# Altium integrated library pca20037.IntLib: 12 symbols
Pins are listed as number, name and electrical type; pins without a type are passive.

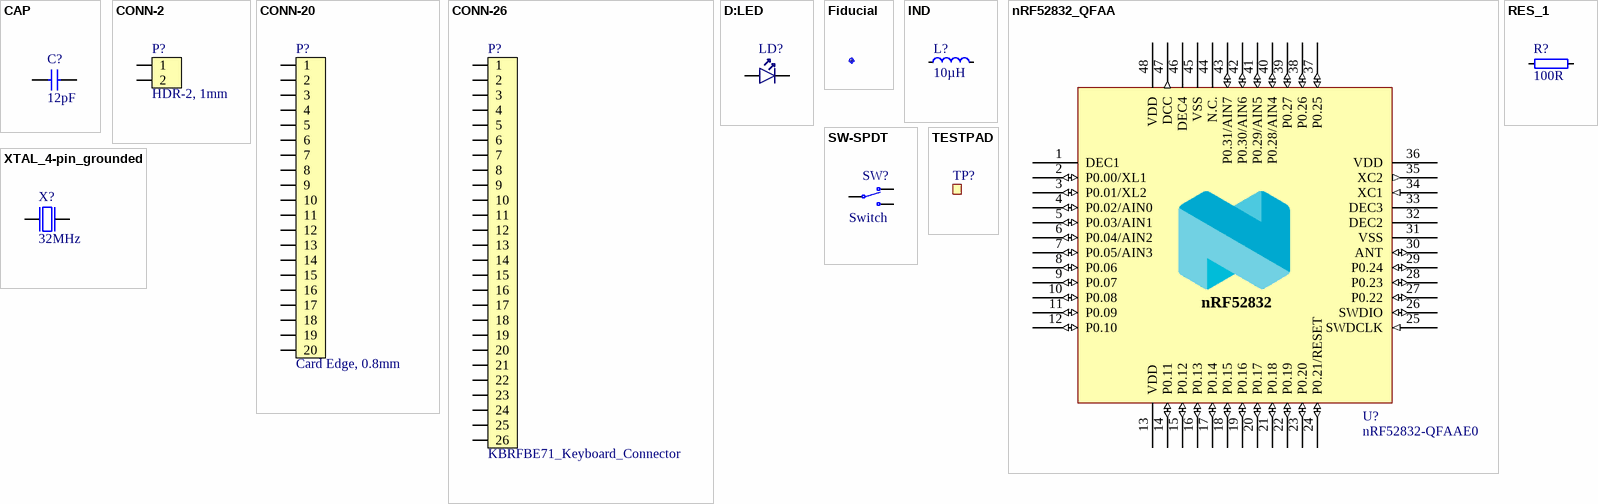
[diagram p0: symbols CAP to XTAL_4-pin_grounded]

## CAP
designator C?, comment 12pF
Capacitor, NP0, ±2%; Part Number: C0402-12p; Part number IPS: 00000002398; Note: 50V; Artikkelnr Noca: 20029159
footprint CAPC1005X04L
pins: 1, 2

## CONN-2
designator P?, comment HDR-2, 1mm
1.0mm pitch connector side entry SMD; Part Number: SM02B-SRSS-TB; Manufacturer: JST; Manufacturer Part Number: SM02B-SRSS-TB(LF)(SN); Part number IPS: 00000007791; Note: JST, Header; Artikkelnr Noca: 55010030
footprint SM02B-SRSS-TB
pins: 1, 2

## CONN-20
designator P?, comment Card Edge, 0.8mm
0.8mm pitch, dual edge, right angle, SMD, card edge connector; Part Number: 10056847-101LF; Manufacturer: FCI; Artikkelnr Noca: N.A.
footprint 10056847-101LF
pins: 1, 2, 3, 4, 5, 6, 7, 8, 9, 10, 11, 12, 13, 14, 15, 16, 17, 18, 19, 20

## CONN-26
designator P?, comment KBRFBE71_Keyboard_Connector
KBRFBE71 Keyboard Connector; Artikkelnr Noca: N.A.
footprint KBRFBE71_Keyboard_Connector
pins: 1, 2, 3, 4, 5, 6, 7, 8, 9, 10, 11, 12, 13, 14, 15, 16, 17, 18, 19, 20, 21, 22, 23, 24, 25, 26

## D:LED
designator LD?, comment L0603R  (value not drawn)
LED 0603, EL19-21SURC; Manufacturer: Everlight; Manufacturer Part Number: EL-19-21SURC/S530-A2/TR8; Part number IPS: N.A.; Note: 39 mcd @ 20 mA; Artikkelnr Noca: 13019043
footprint LED_0603_R
pins: 1 C, 2 A

## Fiducial
designator Fiducual?, comment Fiducial mark  (value not drawn)
Part Number: Fid-Mark; Artikkelnr Noca: N.A.
footprint Fiducial

## IND
designator L?, comment 10µH
Inductor, 80mA, ±10%; Part Number: L0603-10µ; Manufacturer: Taiyo Yuden; Manufacturer Part Number: LBMF1608T100K; Part number IPS: 00000007794; Note: LBMF1608T100K 10µH 80mA 0603; Artikkelnr Noca: 33029314
footprint INDC1608X06L
pins: 1, 2

## nRF52832_QFAA
designator U?, comment nRF52832-QFAAE0
Multi-protocol Bluetooth Low Energy, ANT and 2.4GHz proprietary system-on-chip; Manufacturer: Nordic Semiconductor; Artikkelnr Noca: N.A.
footprint QFN40P600X600X90-48N
pins: 1 DEC1 (power), 2 P0.00/XL1 (io), 3 P0.01/XL2 (io), 4 P0.02/AIN0 (io), 5 P0.03/AIN1 (io), 6 P0.04/AIN2 (io), 7 P0.05/AIN3 (io), 8 P0.06 (io), 9 P0.07 (io), 10 P0.08 (io), 11 P0.09 (io), 12 P0.10 (io), 13 VDD (power), 14 P0.11 (io), 15 P0.12 (io), 16 P0.13 (io), 17 P0.14 (io), 18 P0.15 (io), 19 P0.16 (io), 20 P0.17 (io), 21 P0.18 (io), 22 P0.19 (io), 23 P0.20 (io), 24 P0.21/RESET (io), 25 SWDCLK (in), 26 SWDIO (io), 27 P0.22 (io), 28 P0.23 (io), 29 P0.24 (io), 30 ANT (io), 31 VSS (power), 32 DEC2 (power), 33 DEC3 (power), 34 XC1 (in), 35 XC2 (out), 36 VDD (power), 37 P0.25 (io), 38 P0.26 (io), 39 P0.27 (io), 40 P0.28/AIN4 (io), 41 P0.29/AIN5 (io), 42 P0.30/AIN6 (io), 43 P0.31/AIN7 (io), 44 N.C. (power), 45 VSS (power), 46 DEC4 (power), 47 DCC (out), 48 VDD (power), 49 GND (power) hidden to GND

## RES_1
designator R?, comment 100R
Resistor, ±1%, 0.063W; Part Number: R0402-100; Part number IPS: 00000002811; Note: Chip Res 1%; Artikkelnr Noca: 27049049
footprint RESC1005X04L
pins: 1, 2

## SW-SPDT
designator SW?, comment Switch
SMD slide Switch (ON-ON); Part Number: JS102011SAQN; Manufacturer: C&K Components; Part number IPS: N.A.; Artikkelnr Noca: 50019064
footprint JS102011SAQN
pins: 1 N.C, 2 COM, 3 N.O

## TESTPAD
designator TP?, comment Ø0.7mm,SMD  (value not drawn)  (no BOM)
0.7mm circular SMD testpad; Part Number: TP_SMD_Ø0.7MM; Manufacturer: Nordic Semiconductor; Artikkelnr Noca: N.A.
footprint TP_SMD_Ø0.7mm
pins: 1

## XTAL_4-pin_grounded
designator X?, comment 32MHz
XTAL SMD 2016, 32MHz, Cl=8pF, Tol: ±10ppm, Stab: ±20ppm; Part Number: XTAL_SMD2016_32MHz_8pF_KDS; Manufacturer: KDS; Manufacturer Part Number: DSX211G; Note: XTAL SMD 32.000MHz; Artikkelnr Noca: N.A.
footprint BT-XTAL_2016
pins: 1 inp, 2 GND hidden to GND, 3 out, 4 GND hidden to GND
